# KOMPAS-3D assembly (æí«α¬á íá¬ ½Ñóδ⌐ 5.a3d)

Referenced files in D:\АСКОН работа\Конкурс HOME\06_Сюваев_Сборная модель танка Т90\ДЕТАЛИ\КОРПУС\МЕТАЛЛ\КОРПУС ШТАМПОВКА\БАКИ\: бак левый 5.m3d
Referenced files in D:\АСКОН работа\Конкурс HOME\06_Сюваев_Сборная модель танка Т90\ДЕТАЛИ\ОБЩИЕ ДЕТАЛИ\: шарниры ящиков.m3d, замки ящиков.m3d, ручки баков.m3d
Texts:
  Сборка бак левый 5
